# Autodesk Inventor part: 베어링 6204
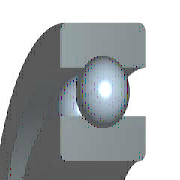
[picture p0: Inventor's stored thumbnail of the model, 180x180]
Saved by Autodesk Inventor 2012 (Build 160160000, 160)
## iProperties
IsCustomPart: 0
Manager: KYOUNG IL JANG
Company: 한국ATC센터
Created: 2009-02
Part Number: 베어링 6204
Material: Steel, Mild
Description: 깊은 그루브 볼 베어링
Document SubType Name: Modeling
Standard: KS B 2023
Standards Organization: KS
Language: ko-KR
Size Designation: 6204 - 20 x 47 x 14
Categories: <MemberInstance><Categories><Category DisplayName="샤프트 부품" InternalName="7f7aeb1f-a693-4053-b835-cee3144e0d98" Mnemonic="SHFT"><Category DisplayName="베어링" Inter
Density: 1 g/cm^3
Checked By: KYOUNG IL JANG
Vendor: CBT Solutions
Designer: KYOUNG IL JANG
Author: KYOUNG IL JANG
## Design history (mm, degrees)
revolve "본체" stored, may be unused: angle "d6" = 90 deg
revolve "볼" stored, may be unused: angle "d7" = 90 deg
pattern_circular "IDS_ARRAYBALL[SIMPL:T]" dims angle "d3" = 360 deg
body "Solid1"
sketch "스케치" dims "d0" = 7.02 (= -0.26 x WD + 0.26 x BD)
  geometry: L1 (3.49, 16.75)-(10.51, 16.75); L2 (7, 16.75)-(7, 13.24); L3 (7, 16.75)-(7, 20.26); L4 (4.392, 14.401)-(0, 14.401); L5 (0, 10)-(14, 10); L6 (4.392, 19.099)-(0, 19.099); L7 (0, 23.5)-(14, 23.5); L8 (14, 10)-(14, 14.401); L9 (9.608, 14.401)-(14, 14.401); L10 (9.608, 19.099)-(14, 19.099); L11 (14, 23.5)-(14, 19.099); L12 (-1.4, 0)-(8.4, 0) reference; L13 (0, -0.3)-(0, 5.3) reference
  constraints: 22 end point, 4 point on line, 2 collinear, 2 perpendicular, 2 symmetric about line, 1 midpoint, 1 parallel, 14 other
  dimensions: "d9" = 20 diameter of L5 L12 (= WD); "d11" = 47 diameter of L7 L12 (= BD); "d12" = 14 distance between parallel lines of L8 L13 (= KB); "d13" = 28.802 diameter of L9 L12 (= 0.326 x BD + 0.674 x WD)
fillet "모깎기1" dims "d1" = 1 (= KRS)
other parameters: "WD" = 20 [user parameter; used in 5 equation terms], "BD" = 47 [user parameter; used in 5 equation terms], "KB" = 14 [user parameter; used in 1 equation term], "KRS" = 1 [user parameter; used in 1 equation term], "d4" = 0, "d5" = 0, "d8" = 0, "d14" = 0, "d15" = 0, "BBA" = 0 [user parameter], "BC0" = 6550000 [user parameter], "BC" = 1.27e+07 [user parameter], "BR" = 23.5 (= 0.5 x BD) [user parameter]
